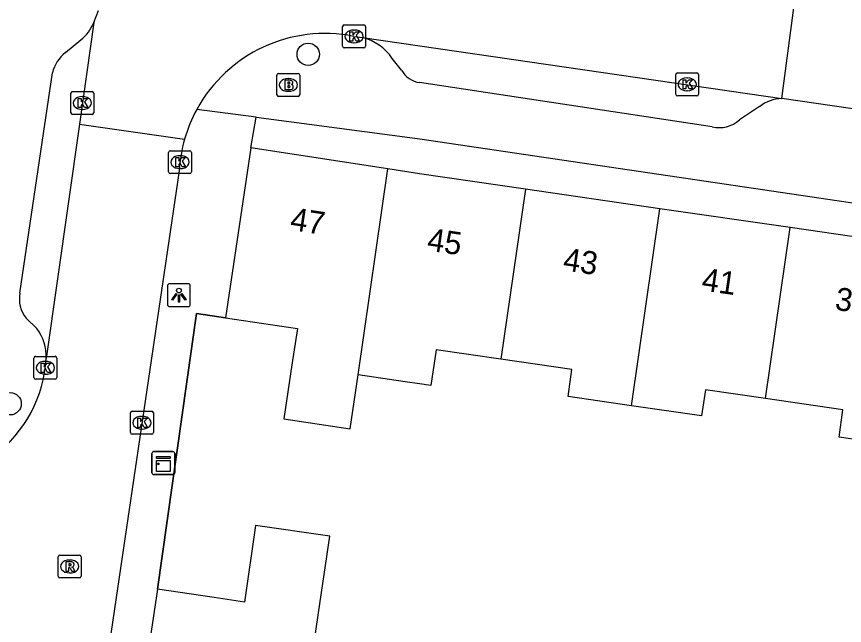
# Model space of a CAD drawing. Extents: x 163686 to 164493, y 382719 to 383870.
# Drawn here: x 163982.4 to 164018.55, y 383029.33 to 383055.9 of the extents above; entities that cross this region are included whole.
import ezdxf

# ---------------------------------------------------------------- set-up
doc = ezdxf.new("R2010")
doc.units = 0
for name, color, linetype in [('IMGEO_Boom', 7, 'Continuous'), ('IMGEO_Brandkraan', 7, 'Continuous'), ('IMGEO_Kast', 7, 'Continuous'), ('IMGEO_Kolk', 7, 'Continuous'), ('IMGEO_Lichtpunt', 7, 'Continuous'), ('IMGEO_Muur', 7, 'Continuous'), ('IMGEO_Pand', 7, 'Continuous'), ('IMGEO_Pand_nummerreeks', 7, 'Continuous'), ('IMGEO_Rijbaan_lokaal_open', 7, 'Continuous'), ('IMGEO_Rioolput', 7, 'Continuous'), ('IMGEO_Voetpad_open', 7, 'Continuous')]:
    doc.layers.add(name, color=color, linetype=linetype)

msp = doc.modelspace()

# ---------------------------------------------------------------- linework, layer by layer
at = {"layer": 'IMGEO_Boom'}
for centre in [(163995.136, 383054.25), (163982.12, 383039.005)]:
    msp.add_circle(centre, 0.489, dxfattribs=at)
at = {"layer": 'IMGEO_Brandkraan'}
for p, q in [((163993.769, 383052.489), (163993.769, 383053.341)), ((163993.844, 383053.415), (163994.696, 383053.415)), ((163994.257, 383053.195), (163994.282, 383053.195)), ((163994.77, 383053.341), (163994.77, 383052.489)), ((163994.28, 383052.635), (163994.255, 383052.635)), ((163994.696, 383052.415), (163993.844, 383052.415))]:
    msp.add_line(p, q, dxfattribs=at)
for points in [[(163993.769, 383052.489), (163993.769, 383053.341)], [(163993.844, 383053.415), (163994.696, 383053.415)], [(163994.77, 383053.341), (163994.77, 383052.489)], [(163994.117, 383053.115), (163994.117, 383052.715), (163994.33, 383052.715)], [(163994.348, 383053.115), (163994.117, 383053.115)], [(163994.296, 383053.034), (163994.242, 383053.034), (163994.242, 383052.958)], [(163994.242, 383052.958), (163994.295, 383052.958)], [(163994.304, 383052.882), (163994.242, 383052.882), (163994.242, 383052.801)], [(163994.242, 383052.801), (163994.304, 383052.801)], [(163994.696, 383052.415), (163993.844, 383052.415)]]:
    msp.add_lwpolyline(points, dxfattribs=at)
for centre, radius, start, end in [((163993.846, 383053.339), 0.0765, 91.552, 178.448), ((163993.846, 383053.339), 0.0765, 91.552, 178.448), ((163994.694, 383053.339), 0.0765, 1.552, 88.448), ((163994.694, 383053.339), 0.0765, 1.552, 88.448), ((163994.297, 383052.996), 0.0379, 267.8285, 90.9355), ((163994.305, 383052.841), 0.0404, 269.8759, 90.5077), ((163994.352, 383052.97), 0.145, 59.4692, 91.5367), ((163994.377, 383053.017), 0.0922, 285.5137, 58.1501), ((163994.382, 383052.825), 0.105, 301.3115, 78.989), ((163993.846, 383052.491), 0.0765, 181.552, 268.448), ((163993.846, 383052.491), 0.0765, 181.552, 268.448), ((163994.336, 383052.966), 0.251, 268.6676, 293.5347), ((163994.694, 383052.491), 0.0765, 271.552, 358.448), ((163994.694, 383052.491), 0.0765, 271.552, 358.448)]:
    msp.add_arc(centre, radius, start, end, dxfattribs=at)
for centre, major_axis, ratio, start_param, end_param in [((163994.256, 383052.915), (-0.387, 0.002), 0.722429, 4.712389, 7.853982), ((163994.281, 383052.915), (-0.39, 0.002), 0.717154, 1.570796, 4.712389)]:
    msp.add_ellipse(centre, major_axis=major_axis, ratio=ratio, start_param=start_param, end_param=end_param, dxfattribs=at)
at = {"layer": 'IMGEO_Kast'}
for p, q in [((163988.388, 383036.914), (163989.229, 383036.914)), ((163989.229, 383036.914), (163988.388, 383036.914)), ((163988.313, 383035.989), (163988.313, 383036.83)), ((163988.313, 383036.83), (163988.313, 383035.989)), ((163989.313, 383036.839), (163989.313, 383035.998)), ((163989.313, 383035.998), (163989.313, 383036.839)), ((163989.238, 383035.914), (163988.397, 383035.914)), ((163988.397, 383035.914), (163989.238, 383035.914))]:
    msp.add_line(p, q, dxfattribs=at)
for points in [[(163988.508, 383036.704), (163989.108, 383036.704), (163989.108, 383036.619), (163988.508, 383036.619), (163988.508, 383036.704)], [(163988.508, 383036.529), (163989.108, 383036.529), (163989.108, 383036.04), (163988.508, 383036.04), (163988.508, 383036.529)]]:
    msp.add_lwpolyline(points, dxfattribs=at)
msp.add_circle((163988.592, 383036.378), 0.0377, dxfattribs=at)
for centre, start, end in [((163988.391, 383036.836), 92.4484, 184.2845), ((163988.391, 383036.836), 92.4484, 184.2845), ((163989.235, 383036.836), 2.4484, 94.2845), ((163989.235, 383036.836), 2.4484, 94.2845), ((163988.391, 383035.992), 182.4484, 274.2845), ((163988.391, 383035.992), 182.4484, 274.2845), ((163989.235, 383035.992), 272.4484, 4.2845), ((163989.235, 383035.992), 272.4484, 4.2845)]:
    msp.add_arc(centre, 0.0779, start, end, dxfattribs=at)
at = {"layer": 'IMGEO_Kolk'}
for p, q in [((163996.637, 383054.605), (163996.637, 383055.457)), ((163996.712, 383055.531), (163997.564, 383055.531)), ((163997.638, 383055.457), (163997.638, 383054.605)), ((163997.125, 383055.311), (163997.15, 383055.311)), ((163997.148, 383054.751), (163997.123, 383054.751)), ((163997.564, 383054.531), (163996.712, 383054.531)), ((164011.181, 383052.512), (164011.181, 383053.364)), ((164011.256, 383053.438), (164012.108, 383053.438)), ((164011.669, 383053.218), (164011.694, 383053.218)), ((164012.182, 383053.364), (164012.182, 383052.512)), ((163984.774, 383051.701), (163984.774, 383052.553)), ((163984.849, 383052.627), (163985.701, 383052.627)), ((163985.775, 383052.553), (163985.775, 383051.701)), ((164011.692, 383052.658), (164011.667, 383052.658)), ((163985.262, 383052.407), (163985.287, 383052.407)), ((164012.108, 383052.438), (164011.256, 383052.438)), ((163985.285, 383051.847), (163985.26, 383051.847)), ((163985.701, 383051.627), (163984.849, 383051.627)), ((163989.038, 383049.119), (163989.038, 383049.971)), ((163989.113, 383050.045), (163989.965, 383050.045)), ((163990.039, 383049.971), (163990.039, 383049.119)), ((163989.526, 383049.825), (163989.551, 383049.825)), ((163989.549, 383049.265), (163989.524, 383049.265)), ((163989.965, 383049.045), (163989.113, 383049.045)), ((163983.16, 383040.145), (163983.16, 383040.997)), ((163983.235, 383041.071), (163984.087, 383041.071)), ((163984.161, 383040.997), (163984.161, 383040.145)), ((163983.648, 383040.851), (163983.673, 383040.851)), ((163983.671, 383040.291), (163983.646, 383040.291)), ((163984.087, 383040.071), (163983.235, 383040.071)), ((163987.376, 383037.747), (163987.376, 383038.599)), ((163987.451, 383038.673), (163988.303, 383038.673)), ((163987.864, 383038.453), (163987.889, 383038.453)), ((163988.377, 383038.599), (163988.377, 383037.747)), ((163988.303, 383037.673), (163987.451, 383037.673)), ((163987.887, 383037.893), (163987.862, 383037.893))]:
    msp.add_line(p, q, dxfattribs=at)
for points in [[(163996.637, 383054.605), (163996.637, 383055.457)], [(163996.712, 383055.531), (163997.564, 383055.531)], [(163997.638, 383055.457), (163997.638, 383054.605)], [(163996.958, 383055.231), (163997.081, 383055.231), (163997.081, 383055.08), (163997.211, 383055.231), (163997.375, 383055.231), (163997.229, 383055.08), (163997.382, 383054.831), (163997.23, 383054.831), (163997.145, 383054.995), (163997.081, 383054.928), (163997.081, 383054.831), (163996.958, 383054.831), (163996.958, 383055.231)], [(163997.564, 383054.531), (163996.712, 383054.531)], [(164011.181, 383052.512), (164011.181, 383053.364)], [(164011.256, 383053.438), (164012.108, 383053.438)], [(164012.182, 383053.364), (164012.182, 383052.512)], [(164011.502, 383053.138), (164011.625, 383053.138), (164011.625, 383052.987), (164011.755, 383053.138), (164011.919, 383053.138), (164011.773, 383052.987), (164011.926, 383052.738), (164011.774, 383052.738), (164011.689, 383052.902), (164011.625, 383052.835), (164011.625, 383052.738), (164011.502, 383052.738), (164011.502, 383053.138)], [(163984.774, 383051.701), (163984.774, 383052.553)], [(163984.849, 383052.627), (163985.701, 383052.627)], [(163985.775, 383052.553), (163985.775, 383051.701)], [(163985.095, 383052.327), (163985.218, 383052.327), (163985.218, 383052.176), (163985.348, 383052.327), (163985.512, 383052.327), (163985.366, 383052.176), (163985.519, 383051.927), (163985.367, 383051.927), (163985.282, 383052.091), (163985.218, 383052.024), (163985.218, 383051.927), (163985.095, 383051.927), (163985.095, 383052.327)], [(164012.108, 383052.438), (164011.256, 383052.438)], [(163985.701, 383051.627), (163984.849, 383051.627)], [(163989.038, 383049.119), (163989.038, 383049.971)], [(163989.113, 383050.045), (163989.965, 383050.045)], [(163990.039, 383049.971), (163990.039, 383049.119)], [(163989.359, 383049.745), (163989.482, 383049.745), (163989.482, 383049.594), (163989.612, 383049.745), (163989.776, 383049.745), (163989.63, 383049.594), (163989.783, 383049.345), (163989.631, 383049.345), (163989.546, 383049.509), (163989.482, 383049.442), (163989.482, 383049.345), (163989.359, 383049.345), (163989.359, 383049.745)], [(163989.965, 383049.045), (163989.113, 383049.045)], [(163983.16, 383040.145), (163983.16, 383040.997)], [(163983.235, 383041.071), (163984.087, 383041.071)], [(163984.161, 383040.997), (163984.161, 383040.145)], [(163983.481, 383040.771), (163983.604, 383040.771), (163983.604, 383040.62), (163983.734, 383040.771), (163983.898, 383040.771), (163983.752, 383040.62), (163983.905, 383040.371), (163983.753, 383040.371), (163983.668, 383040.535), (163983.604, 383040.468), (163983.604, 383040.371), (163983.481, 383040.371), (163983.481, 383040.771)], [(163984.087, 383040.071), (163983.235, 383040.071)], [(163987.376, 383037.747), (163987.376, 383038.599)], [(163987.451, 383038.673), (163988.303, 383038.673)], [(163987.697, 383038.373), (163987.82, 383038.373), (163987.82, 383038.222), (163987.95, 383038.373), (163988.114, 383038.373), (163987.968, 383038.222), (163988.121, 383037.973), (163987.969, 383037.973), (163987.884, 383038.137), (163987.82, 383038.07), (163987.82, 383037.973), (163987.697, 383037.973), (163987.697, 383038.373)], [(163988.377, 383038.599), (163988.377, 383037.747)], [(163988.303, 383037.673), (163987.451, 383037.673)]]:
    msp.add_lwpolyline(points, dxfattribs=at)
for centre, start, end in [((163996.714, 383055.455), 91.552, 178.448), ((163996.714, 383055.455), 91.552, 178.448), ((163997.562, 383055.455), 1.552, 88.448), ((163997.562, 383055.455), 1.552, 88.448), ((163996.714, 383054.607), 181.552, 268.448), ((163996.714, 383054.607), 181.552, 268.448), ((163997.562, 383054.607), 271.552, 358.448), ((163997.562, 383054.607), 271.552, 358.448), ((164011.258, 383053.362), 91.552, 178.448), ((164011.258, 383053.362), 91.552, 178.448), ((164012.106, 383053.362), 1.552, 88.448), ((164012.106, 383053.362), 1.552, 88.448), ((163984.851, 383052.551), 91.552, 178.448), ((163984.851, 383052.551), 91.552, 178.448), ((163985.699, 383052.551), 1.552, 88.448), ((163985.699, 383052.551), 1.552, 88.448), ((164011.258, 383052.514), 181.552, 268.448), ((164011.258, 383052.514), 181.552, 268.448), ((164012.106, 383052.514), 271.552, 358.448), ((164012.106, 383052.514), 271.552, 358.448), ((163984.851, 383051.703), 181.552, 268.448), ((163984.851, 383051.703), 181.552, 268.448), ((163985.699, 383051.703), 271.552, 358.448), ((163985.699, 383051.703), 271.552, 358.448), ((163989.115, 383049.969), 91.552, 178.448), ((163989.115, 383049.969), 91.552, 178.448), ((163989.963, 383049.969), 1.552, 88.448), ((163989.963, 383049.969), 1.552, 88.448), ((163989.115, 383049.121), 181.552, 268.448), ((163989.115, 383049.121), 181.552, 268.448), ((163989.963, 383049.121), 271.552, 358.448), ((163989.963, 383049.121), 271.552, 358.448), ((163983.237, 383040.995), 91.552, 178.448), ((163983.237, 383040.995), 91.552, 178.448), ((163984.085, 383040.995), 1.552, 88.448), ((163984.085, 383040.995), 1.552, 88.448), ((163983.237, 383040.147), 181.552, 268.448), ((163983.237, 383040.147), 181.552, 268.448), ((163984.085, 383040.147), 271.552, 358.448), ((163984.085, 383040.147), 271.552, 358.448), ((163987.453, 383038.597), 91.552, 178.448), ((163987.453, 383038.597), 91.552, 178.448), ((163988.301, 383038.597), 1.552, 88.448), ((163988.301, 383038.597), 1.552, 88.448), ((163987.453, 383037.749), 181.552, 268.448), ((163987.453, 383037.749), 181.552, 268.448), ((163988.301, 383037.749), 271.552, 358.448), ((163988.301, 383037.749), 271.552, 358.448)]:
    msp.add_arc(centre, 0.0765, start, end, dxfattribs=at)
for centre, major_axis, ratio, start_param, end_param in [((163997.124, 383055.031), (-0.387, 0.002), 0.722429, 4.712389, 7.853982), ((163997.149, 383055.031), (-0.39, 0.002), 0.717154, 1.570796, 4.712389), ((164011.668, 383052.938), (-0.387, 0.002), 0.722429, 4.712389, 7.853982), ((164011.693, 383052.938), (-0.39, 0.002), 0.717154, 1.570796, 4.712389), ((163985.261, 383052.127), (-0.387, 0.002), 0.722429, 4.712389, 7.853982), ((163985.286, 383052.127), (-0.39, 0.002), 0.717154, 1.570796, 4.712389), ((163989.525, 383049.545), (-0.387, 0.002), 0.722429, 4.712389, 7.853982), ((163989.55, 383049.545), (-0.39, 0.002), 0.717154, 1.570796, 4.712389), ((163983.647, 383040.571), (-0.387, 0.002), 0.722429, 4.712389, 7.853982), ((163983.672, 383040.571), (-0.39, 0.002), 0.717154, 1.570796, 4.712389), ((163987.863, 383038.173), (-0.387, 0.002), 0.722429, 4.712389, 7.853982), ((163987.888, 383038.173), (-0.39, 0.002), 0.717154, 1.570796, 4.712389)]:
    msp.add_ellipse(centre, major_axis=major_axis, ratio=ratio, start_param=start_param, end_param=end_param, dxfattribs=at)
at = {"layer": 'IMGEO_Lichtpunt'}
for p, q in [((163988.993, 383044.143), (163988.993, 383043.336)), ((163988.993, 383044.143), (163988.993, 383043.336)), ((163989.895, 383044.238), (163989.087, 383044.238)), ((163989.895, 383044.238), (163989.087, 383044.238)), ((163989.989, 383043.336), (163989.989, 383044.143)), ((163989.989, 383043.336), (163989.989, 383044.143)), ((163989.087, 383043.242), (163989.895, 383043.242)), ((163989.087, 383043.242), (163989.895, 383043.242))]:
    msp.add_line(p, q, dxfattribs=at)
for points in [[(163989.367, 383043.807), (163989.406, 383043.779), (163989.218, 383043.517), (163989.18, 383043.544), (163989.367, 383043.807)], [(163989.579, 383043.779), (163989.617, 383043.806), (163989.804, 383043.544), (163989.765, 383043.516), (163989.579, 383043.779)], [(163989.469, 383043.759), (163989.516, 383043.759), (163989.516, 383043.437), (163989.469, 383043.437), (163989.469, 383043.759)]]:
    msp.add_lwpolyline(points, dxfattribs=at)
msp.add_circle((163989.492, 383043.941), 0.0994, dxfattribs=at)
for centre, start, end in [((163989.087, 383044.143), 90, 180), ((163989.087, 383044.143), 90, 180), ((163989.895, 383044.143), 0, 90), ((163989.895, 383044.143), 0, 90), ((163989.087, 383043.336), 180, 270), ((163989.087, 383043.336), 180, 270), ((163989.895, 383043.336), 270, 0), ((163989.895, 383043.336), 270, 360)]:
    msp.add_arc(centre, 0.0946, start, end, dxfattribs=at)
at = {"layer": 'IMGEO_Muur'}
msp.add_lwpolyline([(163988.549, 383030.907), (163990.266, 383042.943), (163991.527, 383042.751)], dxfattribs=at)
at = {"layer": 'IMGEO_Pand'}
for points in [[(163992.635, 383050.168), (163991.527, 383042.751)], [(163998.612, 383049.251), (163992.635, 383050.168)], [(163997.312, 383040.269), (163998.612, 383049.251)], [(164004.619, 383048.366), (164000, 383049.038), (163998.612, 383049.251)], [(164004.619, 383048.366), (164003.544, 383040.943)], [(164010.494, 383047.515), (164004.619, 383048.366)], [(164009.249, 383038.916), (164010.494, 383047.515)], [(164016.184, 383046.691), (164010.494, 383047.515)], [(164015.104, 383039.231), (164016.184, 383046.691)], [(164022.254, 383045.812), (164016.184, 383046.691)], [(163991.527, 383042.751), (163994.663, 383042.283), (163994.427, 383040.7), (163994.076, 383038.346), (163996.971, 383037.913), (163997.312, 383040.269)], [(164003.544, 383040.943), (164000.716, 383041.353), (164000.49, 383039.794), (164000, 383039.868), (163999.373, 383039.961), (163997.312, 383040.269)], [(164009.249, 383038.916), (164006.482, 383039.317), (164006.652, 383040.493), (164003.544, 383040.943)], [(164015.104, 383039.231), (164012.478, 383039.611), (164012.313, 383038.472), (164009.249, 383038.916)], [(164021.001, 383037.156), (164018.311, 383037.546), (164018.484, 383038.741), (164015.104, 383039.231)], [(163995.058, 383026.282), (163995.585, 383029.878), (163996.074, 383033.218), (163992.841, 383033.691), (163992.353, 383030.351), (163991.027, 383030.545), (163988.549, 383030.907)], [(163988.549, 383030.907), (163988.023, 383027.312)]]:
    msp.add_lwpolyline(points, dxfattribs=at)
at = {"layer": 'IMGEO_Rijbaan_lokaal_open'}
for points in [[(164015.819, 383052.322), (164016.437, 383057.059)], [(163985.771, 383055.634), (163985.987, 383056.161)], [(163985.771, 383055.634), (163985.144, 383051.201)], [(163997.121, 383055.034), (163997.502, 383054.979)], [(163997.502, 383054.979), (164000.002, 383054.62), (164015.819, 383052.322)], [(164021.809, 383051.451), (164015.819, 383052.322)], [(163985.144, 383051.201), (163983.699, 383040.977)], [(163985.144, 383051.201), (163989.741, 383050.551)], [(163989.505, 383049.167), (163986.808, 383030.936), (163986.255, 383027.195), (163985.13, 383019.592)]]:
    msp.add_lwpolyline(points, dxfattribs=at)
for centre, radius, start, end in [((163995.86, 383048.794), 6.366, 78.5789, 151.3201), ((163995.829, 383048.805), 6.334, 151.276, 163.9992), ((163995.891, 383048.79), 6.397, 164.0225, 176.6235), ((163978.026, 383041.299), 5.682, 306.9034, 356.756)]:
    msp.add_arc(centre, radius, start, end, dxfattribs=at)
at = {"layer": 'IMGEO_Rioolput'}
for p, q in [((163984.221, 383031.475), (163984.221, 383032.327)), ((163984.296, 383032.401), (163985.148, 383032.401)), ((163985.222, 383032.327), (163985.222, 383031.475)), ((163984.709, 383032.181), (163984.734, 383032.181)), ((163984.732, 383031.621), (163984.707, 383031.621)), ((163985.148, 383031.401), (163984.296, 383031.401))]:
    msp.add_line(p, q, dxfattribs=at)
for points in [[(163984.221, 383031.475), (163984.221, 383032.327)], [(163984.296, 383032.401), (163985.148, 383032.401)], [(163985.222, 383032.327), (163985.222, 383031.475)], [(163984.81, 383032.099), (163984.558, 383032.101), (163984.558, 383031.701)], [(163984.558, 383031.701), (163984.682, 383031.701), (163984.682, 383031.863), (163984.693, 383031.863)], [(163984.736, 383032.02), (163984.682, 383032.02), (163984.682, 383031.939)], [(163984.682, 383031.939), (163984.734, 383031.939)], [(163984.74, 383031.834), (163984.811, 383031.701), (163984.951, 383031.701), (163984.886, 383031.827)], [(163985.148, 383031.401), (163984.296, 383031.401)]]:
    msp.add_lwpolyline(points, dxfattribs=at)
for centre, radius, start, end in [((163984.298, 383032.325), 0.0765, 91.552, 178.448), ((163984.298, 383032.325), 0.0765, 91.552, 178.448), ((163985.146, 383032.325), 0.0765, 1.552, 88.448), ((163985.146, 383032.325), 0.0765, 1.552, 88.448), ((163984.692, 383031.81), 0.0533, 26.0293, 88.6989), ((163984.718, 383032.128), 0.19, 274.7715, 282.9687), ((163984.742, 383031.924), 0.0964, 77.0061, 93.1865), ((163984.756, 383031.981), 0.0378, 276.6634, 79.6772), ((163984.809, 383031.989), 0.109, 350.3612, 89.416), ((163984.807, 383031.989), 0.112, 277.5842, 350.9817), ((163984.791, 383031.774), 0.108, 29.5134, 73.7905), ((163984.298, 383031.477), 0.0765, 181.552, 268.448), ((163984.298, 383031.477), 0.0765, 181.552, 268.448), ((163985.146, 383031.477), 0.0765, 271.552, 358.448), ((163985.146, 383031.477), 0.0765, 271.552, 358.448)]:
    msp.add_arc(centre, radius, start, end, dxfattribs=at)
for centre, major_axis, ratio, start_param, end_param in [((163984.708, 383031.901), (-0.387, 0.002), 0.722429, 4.712389, 7.853982), ((163984.733, 383031.901), (-0.39, 0.002), 0.717154, 1.570796, 4.712389)]:
    msp.add_ellipse(centre, major_axis=major_axis, ratio=ratio, start_param=start_param, end_param=end_param, dxfattribs=at)
at = {"layer": 'IMGEO_Voetpad_open'}
for points in [[(163984.538, 383054.323), (163985.21, 383054.883)], [(163999.207, 383053.555), (163998.799, 383054.074)], [(163982.549, 383043.831), (163983.968, 383053.446)], [(164012.769, 383051.087), (164000, 383053.017)], [(163992.865, 383051.505), (163990.275, 383051.849)], [(164014.845, 383051.966), (164013.962, 383051.395)], [(163992.635, 383050.168), (163992.865, 383051.505)], [(163992.865, 383051.505), (163995.18, 383051.197), (164000.002, 383050.556), (164040.359, 383044.602)], [(163983.288, 383042.283), (163982.817, 383042.739)], [(163991.527, 383042.751), (163990.266, 383042.943), (163988.549, 383030.907)]]:
    msp.add_lwpolyline(points, dxfattribs=at)
for centre, radius, start, end in [((163984.03, 383056.349), 1.882, 308.8186, 337.6616), ((163997.007, 383052.888), 2.149, 33.5034, 76.6847), ((163985.546, 383053.044), 1.629, 128.2475, 165.7094), ((164000.159, 383054.105), 1.1, 210.0239, 261.6673), ((164015.851, 383050.723), 1.599, 91.1619, 128.9931), ((164013.076, 383052.36), 1.31, 256.4248, 312.5274), ((163983.877, 383043.578), 1.352, 169.208, 218.3701), ((163981.62, 383041.041), 2.08, 358.2487, 36.689)]:
    msp.add_arc(centre, radius, start, end, dxfattribs=at)

# ---------------------------------------------------------------- texts
at = {"layer": 'IMGEO_Pand_nummerreeks'}
for s, rotation, p in [('47', 351.2796, (163994.31, 383046.592)), ('45', 351.7393, (164000.291, 383045.693)), ('43', 351.7393, (164006.226, 383044.831)), ('41', 351.7393, (164012.274, 383043.954)), ('39', 351.7393, (164018.097, 383043.108))]:
    msp.add_text(s, height=1, rotation=rotation, dxfattribs=at).set_placement(p)

doc.saveas('drawing.dxf')
